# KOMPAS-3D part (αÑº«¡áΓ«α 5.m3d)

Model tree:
1. Эскиз:1
2. Операция выдавливания:1
     Толщина стенки 1 = 2; Толщина стенки 2 = 8; Расстояние 1 = 1
3. Эскиз:3
4. Операция выдавливания:2
     Толщина стенки 1 = 2; Толщина стенки 2 = 6; Расстояние 1 = 5
5. Эскиз:4
6. Операция выдавливания:3
     Толщина стенки 1 = 2; Толщина стенки 2 = 6; Расстояние 1 = 1
7. Эскиз:5
8. Эскиз:6
9. Операция выдавливания:4
     Толщина стенки 1 = 2; Толщина стенки 2 = 2.5; Расстояние 1 = 50
10. Эскиз:7
11. Вырезать элемент выдавливания:1
     Толщина стенки 2 = 1.5; Расстояние 1 = 40
12. Эскиз:8
13. Операция выдавливания:5
     Толщина стенки 1 = 2; Толщина стенки 2 = 2.5; Расстояние 1 = 50
14. Эскиз:9
15. Вырезать элемент выдавливания:2
     Толщина стенки 2 = 1.5; Расстояние 1 = 40
16. Эскиз:10
17. Операция выдавливания:6
     Толщина стенки 1 = 2; Толщина стенки 2 = 2.5; Расстояние 1 = 10
18. Эскиз:11
19. Операция выдавливания:7
     Толщина стенки 1 = 2; Толщина стенки 2 = 6; Расстояние 1 = 1
20. Эскиз:12
21. Операция выдавливания:8
     Толщина стенки 1 = 2; Толщина стенки 2 = 6; Расстояние 1 = 5
22. Эскиз:13
23. Операция выдавливания:9
     Толщина стенки 1 = 2; Толщина стенки 2 = 8; Расстояние 1 = 1
24. Эскиз:14
25. Вырезать элемент выдавливания:3
     Толщина стенки 2 = 1.5; Расстояние 1 = 23
26. Эскиз:15
27. Вырезать элемент выдавливания:4
     Толщина стенки 2 = 1.5; Расстояние 1 = 1
28. Эскиз:16
29. Вырезать элемент выдавливания:5
     Расстояние 1 = 150
30. Эскиз:17
31. Операция выдавливания:10
     Толщина стенки 1 = 8; Расстояние 1 = 10; Расстояние 2 = 0.4
